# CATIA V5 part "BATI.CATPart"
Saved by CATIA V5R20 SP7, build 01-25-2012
Part number: BATI
Bounding box of the stored display mesh (mm): x -100 to 100, y -120 to 330, z -60 to 180
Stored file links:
  J:\IAO_placube\BATI.CATPart
  J:\IAO_placube\placube_assemblage_IAO.CATProduct
  J:\IAO_placube\COULISSEAU2.CATPart
  J:\IAO_placube\DOIGT.CATPart
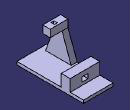
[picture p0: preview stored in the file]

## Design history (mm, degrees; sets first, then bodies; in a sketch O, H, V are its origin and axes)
Set1
  Plane1 "plan_ref": linked copy from another document
  DatumCurve1: linked copy from another document
  Point1 "origine": linked copy from another document
  DatumCurve2 to DatumCurve5: linked copy from another document
  Line1: linked copy from another document
  DatumCurve6 to DatumCurve9: linked copy from another document
Body1 (main body)
  Sketch1 on Plane1, origin (0, 0, 0), H (0, 1, 0), V (0, 0, 1)
    point P1 (-120, -40)
    line L1 (-120, -40) -> (-120, -60)
    line L2 (-120, -60) -> (330, -60)
    line L3 (330, -60) -> (330, -40)
    line L4 (330, -40) -> (240, -40)
    line L5 (240, -40) -> (240, 40)
    line L6 (240, 40) -> (180, 40)
    line L7 (180, 40) -> (180, -40)
    point P8 (180, -40)
    line L8 (180, -40) -> (-120, -40)
    point P9 (-120, -40)
    reference projected line E1 (-66.672, -20) -> (327, -20) from edge of DatumCurve1
    reference projected point E2 (0, 0) from Point1
    reference projected point E3 (0, 0) from Point1
    distance L2 L8 = 20
    distance L8 E1 = 20
    distance L6 L4 = 80
    distance L7 L5 = 60
    distance L1 L3 = 450
    distance L1 E2 = 120
    distance E3 L7 = 180
    vertical: L1 V, L3 V, L5 V, L7 V
    horizontal: L2 H, L4 H, L6 H, L8 H
    coincidence: P8 L4, P9 L1, P1 P9
  Pad1: profile Sketch1, direction (1, 0, 0), length 100, mirrored extent
  Sketch2 on face of Pad1 from Sketch1.L5, origin (0, 240, 0), H (-1, 0, 0), V (0, 0, 1)
    line L1 (-20, 10) -> (20, 10)
    line L2 (20, 10) -> (20, -20)
    line L3 (20, -20) -> (-20, -20)
    line L4 (-20, -20) -> (-20, 10)
    reference projected line E1 (20, -20) -> (20, 10) from edge of DatumCurve2
    reference projected line E2 (-20, -20) -> (-20, 10) from edge of DatumCurve3
    reference projected line E3 (20, 10) -> (-20, 10) from edge of DatumCurve4
    reference projected line E4 (20, -20) -> (-20, -20) from edge of DatumCurve5
    horizontal: L1 H, L3 H
    vertical: L2 V, L4 V
    coincidence: L2 E1, L4 E2, L1 E3, L3 E4
  Pocket1: profile Sketch2, direction (0, -1, 0), through (limit type 6)
  Sketch3 on start face of Pad1, origin (-100, 0, 0), H (0, -1, 0), V (0, 0, 1)
    line L1 (-86.8749, -40) -> (-25, 130)
    line L2 (-25, 130) -> (25, 130)
    line L3 (25, 130) -> (86.8749, -40)
    line L4 (86.8749, -40) -> (-86.8749, -40)
    reference projected line E1 (-180, -40) -> (120, -40) from edge [start face of Pad1 | face of Pad1 from Sketch1.L8]
    reference projected line E2 (0, 29.3446) -> (0, 150) from Line1
    angle L3 L4 = 110
    length L2 = 50
    distance L4 L2 = 170
    horizontal: L2 H
    coincidence: L4 E1
    symmetry: L3 L1 E2
  Pad2: profile Sketch3, direction (1, 0, 0), length 40
  Sketch4 on face of Pad2, origin (-100, 0, 0), H (0, -1, 0), V (0, 0, 1)
    line L1 (-25, 180) -> (25, 180)
    line L2 (25, 180) -> (25, 130)
    line L3 (25, 130) -> (-25, 130)
    line L4 (-25, 130) -> (-25, 180)
    point P3 (25, 130)
    point P4 (-25, 130)
    reference projected point E1 (25, 130) from vertex [face of Pad2 from Sketch3.L2 | start face of Pad2 | face of Pad2 from Sketch3.L3]
    reference projected point E2 (-25, 130) from vertex [start face of Pad2 | face of Pad2 from Sketch3.L1 | face of Pad2 from Sketch3.L2]
    distance L3 L1 = 50
    horizontal: L1 H, L3 H
    vertical: L2 V, L4 V
    coincidence: P3 E1, P4 E2
  Pad3: profile Sketch4, direction (1, 0, 0), length 120
  Sketch5 on face of Pad3 from Sketch4.L1, origin (0, 0, 180), H (1, 0, 0), V (0, 1, 0)
    line L1 (-42, 12) -> (-22, 12)
    line L2 (-22, 12) -> (-22, -12)
    line L3 (-22, -12) -> (-42, -12)
    line L4 (-42, -12) -> (-42, 12)
    reference projected line E1 (-22, -12) -> (-22, 12) from edge of DatumCurve6
    reference projected line E2 (-42, -12) -> (-42, 12) from edge of DatumCurve7
    reference projected line E3 (-22, 12) -> (-42, 12) from edge of DatumCurve8
    reference projected line E4 (-22, -12) -> (-42, -12) from edge of DatumCurve9
    horizontal: L1 H, L3 H
    vertical: L2 V, L4 V
    coincidence: L2 E1, L4 E2, L1 E3, L3 E4
  Pocket2: profile Sketch5, direction (0, 0, -1), through (limit type 6)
